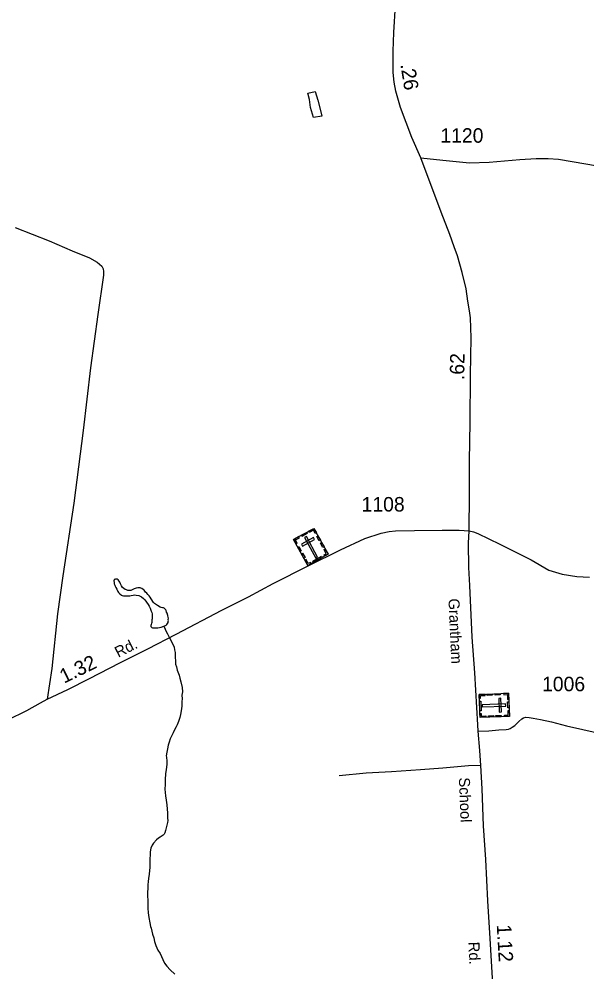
# Model space of a CAD drawing. Extents: x 2206922 to 2357709, y 510027 to 673830.
# Drawn here: x 2241724 to 2246624, y 541278 to 549500 of the extents above; entities that cross this region are included whole.
import ezdxf

# ---------------------------------------------------------------- set-up
doc = ezdxf.new("R2010")
doc.units = 0
for name, color, linetype in [('Exist Cultural Cemetery CELL', 7, 'Continuous'), ('Exist Hydrographic Misc Water Feature', 7, 'Continuous'), ('Exist Road Non-System Type 51', 7, 'Continuous'), ('Exist Road Secondary Mileage Hundredths English Label', 7, 'Continuous'), ('Exist Road Secondary Type 51 Attributed', 7, 'Continuous'), ('Exist Road Secondary Type 51 Label', 7, 'Continuous'), ('Exist Road Secondary Type 51 Number Label', 7, 'Continuous')]:
    doc.layers.add(name, color=color, linetype=linetype)

msp = doc.modelspace()

# ---------------------------------------------------------------- linework, layer by layer
at = {"layer": 'Exist Cultural Cemetery CELL'}
for points in [[(2244092.9, 545009.9), (2244267.8, 545105.1), (2244389.5, 544881.4), (2244214.6, 544786.3)], [(2244288.6, 545067), (2244278.6, 545061.6), (2244263.3, 545089.9), (2244227.6, 545070.5), (2244222.3, 545080.3), (2244267.9, 545105)], [(2244113.6, 544971.9), (2244123.6, 544977.3), (2244108.2, 545005.6), (2244143.8, 545025), (2244138.5, 545034.7), (2244092.9, 545009.9)], [(2244158, 545045.3), (2244203.5, 545070.1), (2244209, 545060.1), (2244163.5, 545035.3)], [(2244161.3, 544969.7), (2244170.2, 544953.2), (2244273.7, 545009.5), (2244264.7, 545025.9)], [(2244202.7, 545036.3), (2244186.3, 545027.4), (2244283.2, 544849.2), (2244299.6, 544858.1)], [(2244313.5, 544997.3), (2244292.8, 545035.4), (2244302.8, 545040.8), (2244323.5, 545002.8)], [(2244149, 544906.7), (2244128.3, 544944.8), (2244138.3, 544950.2), (2244159, 544912.2)], [(2244345, 544939.4), (2244324.3, 544977.5), (2244334.3, 544982.9), (2244355, 544944.9)], [(2244360.4, 544865.5), (2244354.9, 544875.6), (2244374.2, 544886.1), (2244354.9, 544921.6), (2244364.7, 544927), (2244389.5, 544881.4)], [(2244181.1, 544847.7), (2244160.4, 544885.7), (2244170.4, 544891.2), (2244191.1, 544853.1)], [(2244259.6, 544823.8), (2244334.1, 544864.3), (2244339.6, 544854.3), (2244265, 544813.8)], [(2244243.6, 544802.1), (2244238.1, 544812.2), (2244218.8, 544801.7), (2244199.5, 544837.2), (2244189.7, 544831.9), (2244214.5, 544786.3)], [(2245948, 543682.4), (2245955.5, 543483.5), (2245701.1, 543473.8), (2245693.5, 543672.7)], [(2245694.8, 543639.7), (2245706.3, 543640.1), (2245705.5, 543662.1), (2245745.9, 543663.6), (2245745.4, 543674.8), (2245693.6, 543672.8)], [(2245707.2, 543615.8), (2245710.4, 543531), (2245699, 543530.5), (2245695.8, 543615.3)], [(2245763.4, 543675.4), (2245806.7, 543677.1), (2245807.1, 543665.7), (2245763.8, 543664.1)], [(2245830.6, 543678), (2245873.9, 543679.6), (2245874.3, 543668.2), (2245831, 543666.6)], [(2245881.5, 543639), (2245862.9, 543638.3), (2245867.3, 543520.7), (2245886, 543521.4)], [(2245904.7, 543680.8), (2245905.1, 543669.4), (2245937.3, 543670.7), (2245938.8, 543630.1), (2245949.9, 543630.5), (2245948, 543682.4)], [(2245950.8, 543608.4), (2245952.7, 543556.6), (2245941.3, 543556.2), (2245939.4, 543608)], [(2245922.8, 543572.4), (2245922.1, 543591), (2245719.5, 543583.3), (2245720.2, 543564.7)], [(2245912.2, 543481.7), (2245911.8, 543493.1), (2245943.9, 543494.3), (2245942.4, 543534.8), (2245953.5, 543535.3), (2245955.5, 543483.4)], [(2245699.8, 543506.9), (2245711.3, 543507.3), (2245712.1, 543485.4), (2245752.5, 543486.9), (2245753, 543475.8), (2245701.1, 543473.8)], [(2245772.9, 543487.9), (2245816.2, 543489.5), (2245816.6, 543478.2), (2245773.3, 543476.5)], [(2245838.8, 543490.4), (2245882, 543492), (2245882.5, 543480.6), (2245839.2, 543479)]]:
    msp.add_lwpolyline(points, close=True, dxfattribs=at)
at = {"layer": 'Exist Hydrographic Misc Water Feature'}
for points in [[(2244277.4, 548875.7), (2244300.2, 548800.1), (2244325.2, 548710.3), (2244335.4, 548662.5), (2244263.3, 548649.9), (2244238.9, 548735.5), (2244228.4, 548805.6), (2244214.1, 548859.3), (2244277.4, 548875.7)], [(2242971.6, 544262.8), (2242979.8, 544263.2), (2242986, 544267.1), (2242991.7, 544269.1), (2242999.5, 544277.3), (2243005.5, 544285.3), (2243009.4, 544293.2), (2243011.2, 544301.5), (2243011.6, 544311.2), (2243011.2, 544319.3), (2243011.6, 544329.4), (2243011.4, 544335.1), (2243007.1, 544353.2), (2243001.2, 544373.1), (2242996.9, 544383.1), (2242992.8, 544397.1), (2242988.7, 544403), (2242984.6, 544406.9), (2242982.7, 544410.8), (2242976.6, 544417), (2242968.8, 544419), (2242962.6, 544420.7), (2242950.7, 544422.9), (2242940.7, 544426.9), (2242918.3, 544440.3), (2242902.1, 544450.5), (2242892.3, 544458.1), (2242883.9, 544466.2), (2242877.9, 544474), (2242868.1, 544488.1), (2242864.2, 544498), (2242855.8, 544511.9), (2242845.9, 544523.9), (2242833.4, 544535.9), (2242825.9, 544545.6), (2242815.6, 544555.6), (2242801.7, 544571.5), (2242793.5, 544579.2), (2242783.4, 544585.2), (2242775.2, 544589.3), (2242767.4, 544593.3), (2242761.5, 544593), (2242749.6, 544593.2), (2242733.6, 544588.7), (2242717.2, 544582.6), (2242705.5, 544578.7), (2242699.3, 544574.8), (2242687.4, 544570.5), (2242675.8, 544568.6), (2242663.2, 544570.5), (2242649.5, 544574.2), (2242639.5, 544578.1), (2242627.2, 544586), (2242617.3, 544596), (2242606.9, 544609.8), (2242598.9, 544627.7), (2242592.9, 544639.9), (2242586.8, 544649.7), (2242579, 544661.4), (2242570.6, 544667.6), (2242564.6, 544667.6), (2242555, 544667.5), (2242549, 544665.2), (2242544.9, 544663.3), (2242542.9, 544659.2), (2242541, 544655.4), (2242540.8, 544651.4), (2242543.1, 544639.3), (2242545.1, 544627.2), (2242549.2, 544615.3), (2242552.9, 544607.4), (2242559.5, 544595.5), (2242567.5, 544579.6), (2242575.5, 544561.4), (2242581.4, 544551.6), (2242591.9, 544541.9), (2242608.1, 544529.8), (2242613.8, 544526), (2242625.9, 544524.2), (2242643.8, 544522.3), (2242663.9, 544522.5), (2242679.9, 544524.6), (2242692.2, 544526.8), (2242707.7, 544528.9), (2242720, 544530.7), (2242734.2, 544529), (2242758.2, 544524.9), (2242779.9, 544515.2), (2242798.2, 544499.5), (2242810.1, 544487.5), (2242824.2, 544467.5), (2242838.4, 544449.6), (2242846.8, 544433.7), (2242854.8, 544415.9), (2242864.8, 544392.1), (2242868.9, 544378.1), (2242871, 544368), (2242873.2, 544348.2), (2242873.2, 544338.1), (2242871.4, 544326.2)], [(2242871.4, 544326.2), (2242869.1, 544316), (2242869.7, 544304.1), (2242867.9, 544290.2), (2242867.7, 544286.2), (2242864.2, 544276.2), (2242861.9, 544268), (2242861.7, 544264), (2242861.9, 544259.9), (2242863.8, 544256), (2242865.6, 544252.1), (2242870.1, 544250.2), (2242875.7, 544248.1), (2242892.1, 544246.5), (2242903.8, 544246.3), (2242921.6, 544248.5), (2242936, 544250.8), (2242949.9, 544252.7), (2242971.6, 544262.8)], [(2242971.6, 544262.8), (2242983.9, 544235), (2242992.2, 544215.1), (2243004.7, 544195.4), (2243010.2, 544183.2), (2243022.7, 544161.4), (2243035, 544135.6), (2243043, 544119.4), (2243053.3, 544099.7), (2243061.5, 544079.8), (2243065.4, 544057.7), (2243069.7, 544033.9), (2243071.9, 544019.8), (2243071.9, 543991.8), (2243074.2, 543961.9), (2243074.2, 543933.9), (2243080.7, 543910.2), (2243086.9, 543882.1), (2243104.9, 543838.4), (2243111.7, 543814.3), (2243119.5, 543780.3), (2243132, 543732.6), (2243132.4, 543694.4), (2243128.7, 543666.6), (2243131, 543634.6), (2243129.1, 543612.6), (2243127.5, 543570.6), (2243121.7, 543530.5), (2243116, 543500.6), (2243110.3, 543474.3), (2243100.4, 543438.5), (2243088.5, 543410.3), (2243079.1, 543394.2), (2243064.9, 543366), (2243053.5, 543340.1), (2243039.3, 543313.8), (2243027.6, 543290.1), (2243018, 543262), (2243010.2, 543233.9), (2243004.5, 543203.9), (2242998.5, 543173.6), (2242993.2, 543143.7), (2242996.7, 543131.8), (2242997.5, 543098), (2242997.5, 543067.9), (2242991.9, 543023.8), (2242988.5, 542987.8), (2242984.8, 542937.7), (2242982.9, 542895.8), (2242980.9, 542855.9), (2242983.1, 542826), (2242987.8, 542797.7), (2242994.2, 542759.8), (2242998.7, 542719.9), (2243002.4, 542684), (2243004.9, 542650), (2243005.3, 542630), (2243005.3, 542606.1), (2243007.3, 542585.9), (2243003.6, 542568.3), (2242995.8, 542532.1), (2242986.2, 542499.9), (2242980.5, 542478.1), (2242974.5, 542468), (2242966.5, 542457.9), (2242940.9, 542441.4), (2242926.7, 542431.4), (2242908.7, 542417.5), (2242884.9, 542389.1), (2242873.4, 542371), (2242861.5, 542345.2), (2242855.6, 542314.8), (2242853.9, 542285), (2242852.3, 542257), (2242852.9, 542207), (2242850.7, 542178.9), (2242848.8, 542154.8), (2242847, 542123.1), (2242841.4, 542085), (2242838, 542058.8), (2242836.1, 542029), (2242834.5, 541996.8), (2242832.4, 541966.8), (2242833, 541937.1), (2242835.1, 541890.9), (2242835.3, 541869), (2242835.5, 541827.2), (2242837.7, 541787.1), (2242842.7, 541747), (2242850.7, 541703.3), (2242858.9, 541671.2), (2242863.2, 541655.5), (2242875.5, 541605.4), (2242885.5, 541573.5), (2242891.7, 541541.7), (2242904, 541505.8), (2242922.4, 541465.8), (2242940.9, 541436.2), (2242963.2, 541386.2), (2242979.6, 541354.5)], [(2242979.6, 541354.5), (2242999.9, 541328.4), (2243028.2, 541296.9), (2243068.2, 541259.3)]]:
    msp.add_lwpolyline(points, dxfattribs=at)
at = {"layer": 'Exist Road Non-System Type 51'}
for points in [[(2241690.2, 547701), (2241983, 547585.3), (2242181.6, 547501.1), (2242330.1, 547438.3), (2242398.3, 547400.8), (2242438.6, 547367.2), (2242448.7, 547343.4), (2242452.9, 547321.3), (2242451.3, 547291.3), (2242402.4, 546950.4), (2242340.7, 546491.3), (2242277.3, 545948.7), (2242195, 545322.1), (2242101.6, 544696), (2242054.8, 544368.8), (2242006.4, 543896.3), (2241964.7, 543630.9)], [(2245685.7, 543355.5), (2245776.7, 543359.3), (2245864.5, 543365.7), (2245925.5, 543370.8), (2245945.9, 543373.3), (2245959.9, 543379.7), (2245979, 543389.9), (2246000.6, 543405.1), (2246036.2, 543438.2), (2246060.4, 543461.2), (2246076.9, 543471.3), (2246096, 543475.2), (2246124, 543473.9), (2246159.6, 543467.5), (2246223.3, 543456.1), (2246317.4, 543435.7), (2246447.2, 543402.6), (2246729.7, 543337.7)], [(2245708, 543060.1), (2245601.1, 543056.3), (2245379.7, 543035.3), (2245186.9, 543022), (2244936.9, 543004.8), (2244719.3, 542993.3), (2244486.5, 542970.4)]]:
    msp.add_lwpolyline(points, dxfattribs=at)
at = {"layer": 'Exist Road Secondary Type 51 Attributed'}
for points in [[(2245189.1, 548301.5), (2245112.9, 548477.4), (2245016, 548736.4), (2244975.9, 548877.7), (2244959.3, 548953.9), (2244951, 549039.1), (2244951, 549136), (2244951, 549221.9), (2244957.9, 549382.6), (2244970.6, 549619.8)], [(2245607.8, 545083.2), (2245609.1, 545396.6), (2245610.3, 545687.1), (2245615.4, 546019.6), (2245619.2, 546426.8), (2245624.3, 546750.4), (2245617.9, 546921.7), (2245610.3, 546982.6), (2245597.2, 547066.9), (2245582.4, 547172.9), (2245547.6, 547312.5), (2245506.4, 547458.1), (2245477.7, 547535.8), (2245441, 547639.6), (2245364.9, 547834), (2245189.1, 548301.5)], [(2245189.1, 548301.5), (2245380.1, 548282.8), (2245611.3, 548260.6), (2245780.2, 548266.2), (2246043.4, 548288), (2246185.8, 548295.3), (2246288.2, 548298), (2246378.2, 548289.7), (2246833.7, 548212.9)], [(2241626.9, 543452.5), (2241791.2, 543534.9), (2241909.5, 543598.8), (2241964.7, 543630.9), (2242144.6, 543714.6), (2242331.8, 543809.5), (2242592.1, 543946.4), (2242835.7, 544065.6), (2243080.5, 544192.5), (2243473.6, 544400.6), (2243704.4, 544514.8), (2243916.1, 544629), (2244216.7, 544782.5), (2244495.7, 544919.1), (2244707.4, 545017.2), (2244846.9, 545062.9), (2244917.9, 545078.1), (2244972.5, 545084.5), (2245134.8, 545088.3), (2245373.2, 545090.8), (2245520.3, 545089.5), (2245607.8, 545083.2)], [(2245867.7, 540496.2), (2245860.1, 540558.6), (2245843.1, 540744.1), (2245816.2, 541077.7), (2245789.1, 541566.1), (2245769.6, 541893), (2245750.8, 542248.6), (2245732.4, 542538.3), (2245719.8, 542858.1), (2245708, 543060.1), (2245699.1, 543187.8), (2245685.7, 543355.5), (2245681.3, 543409.6), (2245656, 543858.8), (2245631.9, 544167.1), (2245614.1, 544611.2), (2245605.3, 544768.5), (2245602.7, 544979.1), (2245607.8, 545083.2)], [(2245607.8, 545083.2), (2245645.8, 545076.8), (2245682.6, 545060.3), (2245872.8, 544969), (2246142.9, 544834.5), (2246294.2, 544743.7), (2246410.5, 544708.8), (2246536.4, 544689.9), (2246646.5, 544684.6)]]:
    msp.add_lwpolyline(points, dxfattribs=at)

# ---------------------------------------------------------------- texts
at = {"layer": 'Exist Road Secondary Mileage Hundredths English Label'}
for s, rotation, p in [('.26', 279.09628, (2245013.4, 549107.6)), ('.62', 89.04824, (2245564.2, 546383.8)), ('1.32', 25.94951, (2242111.9, 543764.5)), ('1.12', 273.17322, (2245845.1, 541685.5))]:
    msp.add_text(s, height=125, rotation=rotation, dxfattribs=at).set_placement(p)
at = {"layer": 'Exist Road Secondary Type 51 Label'}
for s, rotation, p in [('Grantham', 272.65891, (2245427.9, 544498.6)), ('Rd.', 27.03666, (2242579.4, 543987.6)), ('School', 272.25598, (2245518.1, 542954.8)), ('Rd.', 272.26005, (2245600.9, 541536.8))]:
    msp.add_text(s, height=95, rotation=rotation, dxfattribs=at).set_placement(p)
at = {"layer": 'Exist Road Secondary Type 51 Number Label'}
for s, p in [('1120', (2245358.7, 548432.7)), ('1108', (2244679.2, 545250.8)), ('1006', (2246236, 543700.2))]:
    msp.add_text(s, height=125, dxfattribs=at).set_placement(p)

doc.saveas('drawing.dxf')
